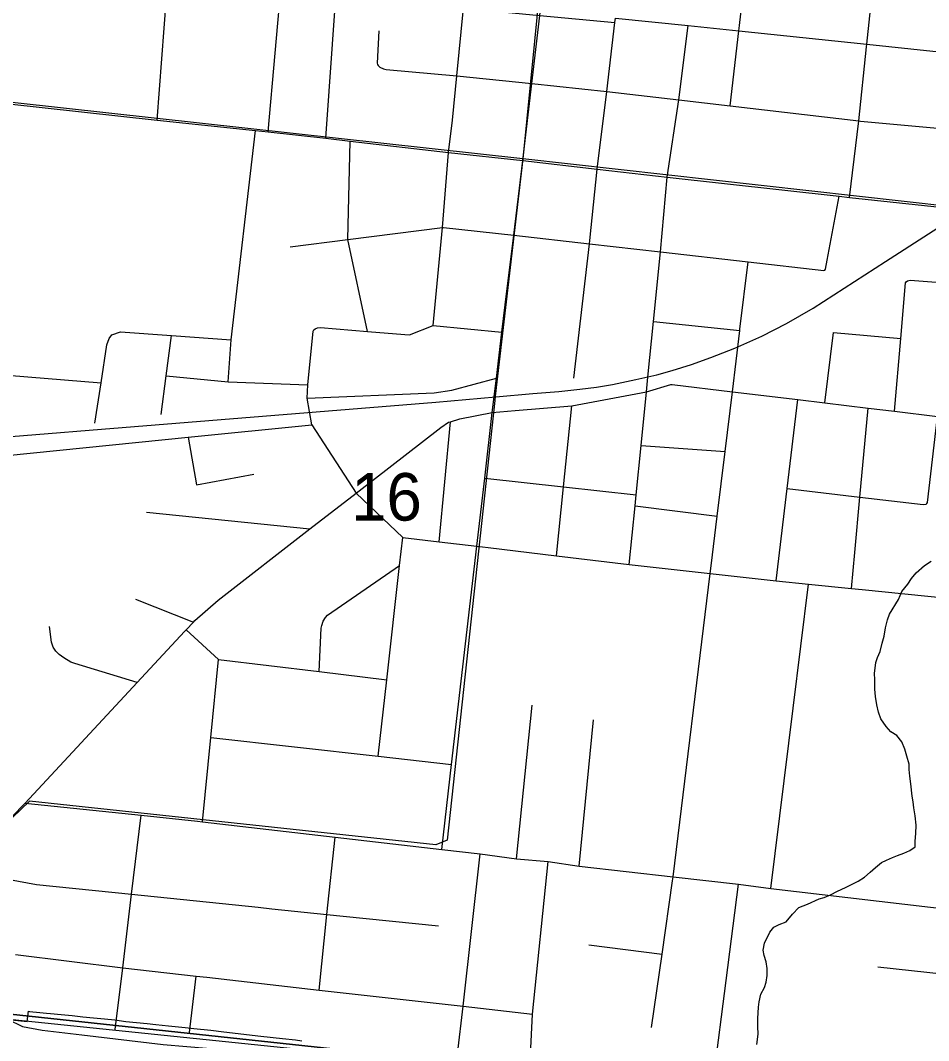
# Model space of a CAD drawing. Extents: x 0 to 34, y 0 to 22.
# Drawn here: x 3.3871 to 3.7866, y 18.456 to 18.905 of the extents above; entities that cross this region are included whole.
import ezdxf

# ---------------------------------------------------------------- set-up
doc = ezdxf.new("R2010")
doc.units = 0
for name, color, linetype in [('GM_X_City_Street', 7, 'Continuous'), ('GM_X_Corporation', 7, 'Continuous'), ('GM_X_County_Road', 7, 'Continuous'), ('GM_X_Minor_River', 7, 'Continuous'), ('GM_X_Rail_Line', 7, 'Continuous'), ('GM_X_Section', 7, 'Continuous'), ('GM_X_Section_Text', 7, 'Continuous')]:
    doc.layers.add(name, color=color, linetype=linetype)

msp = doc.modelspace()

# ---------------------------------------------------------------- linework, layer by layer
at = {"layer": 'GM_X_City_Street'}
for p, q in [((3.4472, 18.86107), (3.45508, 18.96348)), ((3.66556, 18.77247), (3.70356, 18.76846)), ((3.74099, 18.73661), (3.74477, 18.76767)), ((3.74477, 18.76767), (3.77434, 18.76491)), ((3.57127, 18.67553), (3.57627, 18.72833)), ((3.46083, 18.72151), (3.4646, 18.70062)), ((3.66014, 18.71789), (3.69706, 18.71519)), ((3.4646, 18.70062), (3.48981, 18.70528)), ((3.44249, 18.6885), (3.51446, 18.68115)), ((3.65749, 18.6913), (3.69359, 18.68679)), ((3.43773, 18.65024), (3.4632, 18.64018)), ((3.60533, 18.536), (3.61214, 18.60361)), ((3.63291, 18.53276), (3.63912, 18.59719)), ((3.6372, 18.49805), (3.66936, 18.49403)), ((3.46152, 18.4595), (3.46435, 18.48435))]:
    msp.add_line(p, q, dxfattribs=at)
for points in [[(3.56869, 18.77065), (3.57247, 18.8108), (3.57275, 18.81379), (3.57543, 18.84685), (3.5772, 18.861), (3.57904, 18.88058), (3.58206, 18.91037), (3.58215, 18.91126), (3.58571, 18.94648), (3.58611, 18.95041), (3.59335, 19.02194), (3.59511, 19.03934), (3.59743, 19.06219)], [(3.69927, 18.86737), (3.70312, 18.9004), (3.70338, 18.90268), (3.70726, 18.93597), (3.71037, 18.97363), (3.71287, 19.00397)], [(3.52142, 18.8531), (3.52577, 18.91528), (3.5263, 18.91603), (3.52707, 18.91638), (3.5286, 18.91652), (3.53392, 18.91676), (3.53493, 18.917), (3.53561, 18.91752), (3.536, 18.91807), (3.53627, 18.91936), (3.54071, 18.95577), (3.54266, 18.97178), (3.54437, 18.98582)], [(3.75175, 18.82704), (3.7559, 18.86073), (3.75932, 18.89334), (3.75945, 18.89447), (3.76309, 18.92923)], [(3.58206, 18.91037), (3.61553, 18.90716), (3.64859, 18.90398), (3.64882, 18.90594), (3.68079, 18.90274), (3.70312, 18.9004), (3.75945, 18.89447), (3.81062, 18.88909), (3.82738, 18.88733), (3.85424, 18.8845), (3.88618, 18.88114)], [(3.63056, 18.74753), (3.63738, 18.80669), (3.63754, 18.80809), (3.64078, 18.83954), (3.6451, 18.87372), (3.64859, 18.90398)], [(3.65493, 18.66551), (3.65749, 18.6913), (3.65798, 18.69621), (3.66014, 18.71789), (3.66249, 18.74155), (3.66312, 18.74798), (3.66556, 18.77247), (3.6686, 18.80314), (3.67161, 18.83592), (3.67678, 18.87001), (3.68079, 18.90274)], [(3.5448, 18.9003), (3.54404, 18.8861), (3.54414, 18.88558), (3.5444, 18.88515), (3.54524, 18.88438), (3.54679, 18.88362), (3.54798, 18.8833), (3.57904, 18.88058)], [(3.57904, 18.88058), (3.612, 18.87716), (3.6451, 18.87372), (3.67678, 18.87001), (3.69927, 18.86737), (3.7559, 18.86073), (3.75659, 18.86065), (3.80661, 18.85604)], [(3.47842, 18.74592), (3.47985, 18.76433), (3.49052, 18.85647)], [(3.53969, 18.76809), (3.53107, 18.80856), (3.53219, 18.85179)], [(3.74129, 18.79551), (3.74197, 18.79948), (3.74732, 18.82762)], [(3.50578, 18.80538), (3.53107, 18.80856), (3.57275, 18.81379), (3.57319, 18.81385), (3.60407, 18.81047), (3.63738, 18.80669), (3.6686, 18.80314), (3.70726, 18.79874), (3.74052, 18.79496), (3.74098, 18.79508), (3.74129, 18.79551)], [(3.66476, 18.46179), (3.66936, 18.49403), (3.67395, 18.52623), (3.67421, 18.52805), (3.6905, 18.66153), (3.69092, 18.66496), (3.69359, 18.68679), (3.69706, 18.71519), (3.70027, 18.7415), (3.70356, 18.76846), (3.70363, 18.76901), (3.70726, 18.79874)], [(3.77161, 18.73294), (3.77434, 18.76491), (3.77644, 18.78944), (3.77681, 18.78997), (3.77734, 18.79036), (3.77856, 18.79071)], [(3.77856, 18.79071), (3.80314, 18.7887), (3.80907, 18.78822), (3.82706, 18.78674)], [(3.51351, 18.74461), (3.51587, 18.7682), (3.51615, 18.76872), (3.51678, 18.76922), (3.51778, 18.76968), (3.51914, 18.76987), (3.53969, 18.76809), (3.55621, 18.76667), (3.55829, 18.76661), (3.56869, 18.77065), (3.59893, 18.76779)], [(3.41987, 18.72771), (3.42255, 18.7454), (3.42509, 18.76214), (3.42611, 18.76497), (3.42729, 18.76665)], [(3.42729, 18.76665), (3.43112, 18.76788), (3.45351, 18.76624), (3.47985, 18.76433)], [(3.44901, 18.7315), (3.45121, 18.74849), (3.45351, 18.76624)], [(3.31561, 18.7575), (3.37404, 18.74945), (3.42255, 18.7454)], [(3.45121, 18.74849), (3.47842, 18.74592), (3.51351, 18.74461)], [(3.51318, 18.73873), (3.56905, 18.74106), (3.57686, 18.74218), (3.5965, 18.74756)], [(3.51527, 18.72699), (3.51318, 18.73873), (3.51351, 18.74461)], [(3.59466, 18.73233), (3.60467, 18.73321), (3.62969, 18.73539), (3.66249, 18.74155), (3.6732, 18.74469), (3.67385, 18.74468), (3.70027, 18.7415), (3.72908, 18.73805), (3.74099, 18.73661), (3.75996, 18.73434), (3.77161, 18.73294), (3.79056, 18.73066), (3.8038, 18.72907), (3.82248, 18.72683)], [(3.71954, 18.65829), (3.7244, 18.6989), (3.72908, 18.73805)], [(3.62289, 18.66935), (3.62601, 18.6997), (3.62969, 18.73539)], [(3.75262, 18.65493), (3.75409, 18.67081), (3.75634, 18.69519), (3.75996, 18.73434)], [(3.78424, 18.69195), (3.78556, 18.69211), (3.78587, 18.69237), (3.7861, 18.69277), (3.79056, 18.73066)], [(3.32317, 18.70765), (3.46083, 18.72151), (3.51527, 18.72699)], [(3.51527, 18.72699), (3.53478, 18.69695), (3.55527, 18.67744), (3.57127, 18.67553), (3.58785, 18.67354), (3.59286, 18.67294)], [(3.59132, 18.70349), (3.62601, 18.6997), (3.65798, 18.69621)], [(3.7244, 18.6989), (3.75634, 18.69519), (3.78424, 18.69195)], [(3.5444, 18.58112), (3.5482, 18.6148), (3.55387, 18.66511), (3.55527, 18.67744)], [(3.59286, 18.67294), (3.62289, 18.66935), (3.65493, 18.66551), (3.6905, 18.66153), (3.71954, 18.65829), (3.73372, 18.65685), (3.75262, 18.65493), (3.75732, 18.65445)], [(3.51848, 18.61835), (3.51941, 18.63743), (3.51966, 18.63867), (3.52029, 18.64055), (3.52128, 18.64217), (3.52221, 18.64325), (3.55387, 18.66511)], [(3.7172, 18.52285), (3.72699, 18.60226), (3.73372, 18.65685)], [(3.75732, 18.65445), (3.81376, 18.64871), (3.83508, 18.64638), (3.85603, 18.64409), (3.88671, 18.64074), (3.93852, 18.63508), (3.97824, 18.63226)], [(3.43838, 18.61353), (3.41094, 18.62188), (3.40932, 18.6225), (3.40614, 18.62449), (3.40413, 18.62585), (3.40261, 18.62743), (3.40149, 18.62912), (3.40081, 18.63128), (3.39984, 18.63814)], [(3.45992, 18.63675), (3.47426, 18.62362), (3.51848, 18.61835), (3.5482, 18.6148)], [(3.46721, 18.55223), (3.47088, 18.58931), (3.47426, 18.62362)], [(3.47088, 18.58931), (3.5444, 18.58112), (3.57673, 18.57752)], [(3.42877, 18.46079), (3.43206, 18.488), (3.43597, 18.52036), (3.44017, 18.55511)], [(3.51843, 18.47822), (3.52194, 18.51151), (3.52552, 18.54552)], [(3.37148, 18.54245), (3.37268, 18.53619), (3.37312, 18.53488), (3.37399, 18.53303), (3.37519, 18.53151), (3.37626, 18.53046), (3.37922, 18.52824), (3.38224, 18.52688), (3.39414, 18.52467), (3.43597, 18.52036), (3.49166, 18.51463)], [(3.57943, 18.45), (3.58178, 18.47106), (3.58929, 18.53818)], [(3.69212, 18.44016), (3.69752, 18.48247), (3.70293, 18.52478)], [(3.49166, 18.51463), (3.49773, 18.51401), (3.52194, 18.51151), (3.52912, 18.51077), (3.57098, 18.50647)], [(3.3849, 18.49386), (3.43206, 18.488), (3.46435, 18.48435), (3.46905, 18.48381), (3.51843, 18.47822), (3.58178, 18.47106), (3.6123, 18.4676)], [(3.76428, 18.48836), (3.79383, 18.48518), (3.79579, 18.48497), (3.86922, 18.4776)], [(3.37663, 18.46678), (3.38145, 18.46542), (3.38795, 18.46221), (3.39658, 18.46049), (3.41409, 18.45851), (3.44984, 18.45432), (3.47072, 18.45243), (3.49053, 18.45013), (3.4967, 18.44988), (3.5041, 18.44988), (3.51322, 18.44988), (3.5184, 18.44964), (3.52999, 18.44816), (3.54388, 18.44668), (3.57693, 18.44322), (3.61077, 18.4393)]]:
    msp.add_lwpolyline(points, dxfattribs=at)
at = {"layer": 'GM_X_Corporation'}
msp.add_lwpolyline([(3.36503, 18.46704), (3.39008, 18.46439), (3.39066, 18.46886), (3.3911, 18.46882), (3.39562, 18.46838), (3.39856, 18.4681), (3.40026, 18.46793), (3.40498, 18.46745), (3.40977, 18.46697), (3.41447, 18.46649), (3.41922, 18.46601), (3.42403, 18.46553), (3.42866, 18.46506), (3.4334, 18.46442), (3.44278, 18.46346), (3.44657, 18.46307), (3.4522, 18.46249), (3.45957, 18.46174), (3.4634, 18.46134), (3.47086, 18.46049), (3.47652, 18.45985), (3.4803, 18.45942), (3.48656, 18.4587), (3.4928, 18.45788), (3.50242, 18.45684), (3.50807, 18.45623), (3.51089, 18.45592)], dxfattribs=at)
at = {"layer": 'GM_X_County_Road'}
msp.add_line((3.6123, 18.4676), (3.61927, 18.53473), dxfattribs=at)
for points in [[(3.49611, 18.8559), (3.50536, 18.95994), (3.50942, 18.99817), (3.51469, 19.04781), (3.5167, 19.06668)], [(3.5724, 18.54012), (3.57673, 18.57752), (3.58785, 18.67354), (3.59132, 18.70349), (3.59466, 18.73233), (3.5965, 18.74756), (3.59893, 18.76779), (3.60039, 18.77985), (3.60407, 18.81047), (3.60803, 18.8433), (3.612, 18.87716), (3.61553, 18.90716), (3.61956, 18.94148)], [(3.37709, 18.86886), (3.38062, 18.86843), (3.4472, 18.86107), (3.49052, 18.85647), (3.49611, 18.8559), (3.52142, 18.8531), (3.53219, 18.85179), (3.57543, 18.84685), (3.60803, 18.8433), (3.64078, 18.83954), (3.67161, 18.83592), (3.74732, 18.82762), (3.75175, 18.82704), (3.80272, 18.82153), (3.8088, 18.82088), (3.83059, 18.81841), (3.83451, 18.81798)], [(3.38331, 18.55448), (3.38923, 18.56049), (3.43838, 18.61353), (3.45921, 18.63601), (3.45992, 18.63675), (3.4632, 18.64018), (3.46385, 18.64085), (3.47409, 18.64977), (3.51446, 18.68115), (3.53478, 18.69695), (3.57198, 18.72586), (3.57544, 18.72807), (3.57627, 18.72833), (3.5804, 18.72968), (3.59466, 18.73233)], [(3.38923, 18.56049), (3.44017, 18.55511), (3.465, 18.55248), (3.46721, 18.55223), (3.52552, 18.54552), (3.5724, 18.54012), (3.58929, 18.53818), (3.60533, 18.536), (3.61927, 18.53473), (3.63291, 18.53276), (3.67421, 18.52805), (3.70293, 18.52478), (3.7172, 18.52285), (3.79869, 18.51333), (3.82059, 18.51072), (3.87108, 18.50515), (3.9076, 18.50112), (3.95907, 18.49544)], [(3.61077, 18.4393), (3.61096, 18.44076), (3.6123, 18.4676)]]:
    msp.add_lwpolyline(points, dxfattribs=at)
at = {"layer": 'GM_X_Minor_River'}
for points in [[(3.76381, 18.60374), (3.7632, 18.60738), (3.76295, 18.61062), (3.76292, 18.61481), (3.76284, 18.61766), (3.76312, 18.61993), (3.76341, 18.62239), (3.76407, 18.62464), (3.76531, 18.62725), (3.76621, 18.63083), (3.7671, 18.63402), (3.76762, 18.63761), (3.76852, 18.64118), (3.76938, 18.64362), (3.77343, 18.65011), (3.7749, 18.65366), (3.7775, 18.65678), (3.77912, 18.65937), (3.78111, 18.66176), (3.78485, 18.66503), (3.78778, 18.667)], [(3.71099, 18.45425), (3.71127, 18.45652), (3.71156, 18.45898), (3.71148, 18.46202), (3.71144, 18.46563), (3.71183, 18.47075), (3.71211, 18.47302), (3.71281, 18.47641), (3.71445, 18.47939), (3.71511, 18.48164), (3.71561, 18.48466), (3.71554, 18.4877), (3.71508, 18.49057), (3.71424, 18.49346), (3.71377, 18.49576), (3.71445, 18.49878), (3.71674, 18.50362), (3.71853, 18.50583), (3.72086, 18.50706), (3.72395, 18.50826), (3.72674, 18.51157), (3.72951, 18.5145), (3.73338, 18.51605), (3.73841, 18.51831), (3.74071, 18.51897), (3.74342, 18.52019), (3.74652, 18.52177), (3.75, 18.52334), (3.7533, 18.52491), (3.75563, 18.52615), (3.75836, 18.52793), (3.76091, 18.53011), (3.76327, 18.5321), (3.76583, 18.53428), (3.76815, 18.53532), (3.77067, 18.53655), (3.77298, 18.5374), (3.77568, 18.53843), (3.77839, 18.53965), (3.78073, 18.54126), (3.78064, 18.54374), (3.78097, 18.54714), (3.78111, 18.55075), (3.7807, 18.55495), (3.78008, 18.5584), (3.7798, 18.56107), (3.77933, 18.56356), (3.77878, 18.56891), (3.77835, 18.57234), (3.77808, 18.57521), (3.77799, 18.57768), (3.77698, 18.58115), (3.77616, 18.58422), (3.77477, 18.58751), (3.77259, 18.59026), (3.77, 18.59189), (3.768, 18.59425), (3.76566, 18.59758), (3.76464, 18.60048), (3.76381, 18.60374)]]:
    msp.add_lwpolyline(points, dxfattribs=at)
at = {"layer": 'GM_X_Rail_Line'}
for p, q in [((3.60814, 18.84411), (3.596, 18.73953)), ((3.80331, 18.8222), (3.60814, 18.84411)), ((3.596, 18.73953), (3.59579, 18.73771))]:
    msp.add_line(p, q, dxfattribs=at)
for points in [[(3.60814, 18.84411), (3.10148, 18.89993), (3.08381, 18.90261), (3.06684, 18.91815), (3.02008, 19.01178), (3.00463, 19.02884), (2.98028, 19.04141), (2.95907, 19.04455), (2.93237, 19.04848), (2.86797, 19.05398), (2.84205, 19.04376), (2.82869, 19.02805), (2.82778, 19.02696)], [(3.6182, 18.94624), (3.60814, 18.84411)], [(3.12688, 18.70119), (3.19154, 18.70632), (3.42271, 18.72511), (3.5698, 18.73692), (3.59626, 18.73928), (3.61255, 18.74074), (3.62394, 18.74171), (3.63314, 18.74261), (3.64047, 18.74352), (3.64761, 18.74473), (3.65785, 18.74685), (3.66705, 18.74903), (3.67383, 18.75091), (3.68237, 18.75357), (3.69085, 18.75666), (3.70139, 18.76066), (3.71326, 18.76605), (3.72403, 18.77162), (3.73584, 18.77828), (3.76769, 18.79881), (3.80342, 18.82194)], [(3.59579, 18.73771), (3.57485, 18.5442), (3.56984, 18.54205), (3.39113, 18.56139), (3.3461, 18.51827)], [(4.31008, 18.28146), (4.20438, 18.36289), (4.18895, 18.37397), (4.16841, 18.37909), (4.02522, 18.39882), (3.29119, 18.47469), (3.25437, 18.47634)]]:
    msp.add_lwpolyline(points, dxfattribs=at)
at = {"layer": 'GM_X_Section'}
msp.add_lwpolyline([(3.33585, 18.97757), (3.84478, 18.91854), (3.78896, 18.4239), (3.29405, 18.47716)], close=True, dxfattribs=at)
msp.add_lwpolyline([(3.2415, 17.96998), (3.29405, 18.47716), (3.78896, 18.4239), (3.73932, 17.95816)], dxfattribs=at)

# ---------------------------------------------------------------- texts
at = {"layer": 'GM_X_Section_Text'}
msp.add_text('16', height=0.020928, rotation=0, dxfattribs=at).set_placement((3.53254, 18.68481))

doc.saveas('drawing.dxf')
